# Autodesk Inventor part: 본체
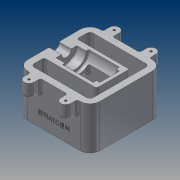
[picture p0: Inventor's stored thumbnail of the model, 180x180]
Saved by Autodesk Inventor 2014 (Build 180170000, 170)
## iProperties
Created: 2018-01
Part Number: 본체
Material: 알루미늄 6061
Document SubType Name: Modeling
Designer: user
Mass: 999.317 g
Surface Area: 835.945 cm^2
Volume: 368.752 cm^3
Density: 2.71 g/cm^3
Appearance: 알루미늄 - 평지
Author: user
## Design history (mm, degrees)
sketch "스케치2"
  geometry: L1 (-55, -55)-(55, -55); L2 (55, -55)-(55, 55); L3 (55, 55)-(-55, 55); L4 (-55, 55)-(-55, -55); L5 (-55, -55)-(55, 55); L6 (55, -55)-(-55, 55); L7 (-45, 45)-(45, 45); L8 (45, 45)-(45, -45); L9 (45, -45)-(-45, -45); L10 (-45, -45)-(-45, 45); L11 (-45, 45)-(45, -45); L12 (45, 45)-(-45, -45); 1 further point
  constraints: 24 end point, 4 midpoint, 4 parallel, 2 horizontal, 2 perpendicular
  dimensions: "d0" = 110 distance of L2.end L3.end; "d1" = 110 distance of L1.end L2.end; "d2" = 90 distance of L7.start L7.end; "d3" = 90 distance of L7.end L8.end
extrude "돌출1" new body sketch "스케치2" distance "d4" = 65; taper "d5" = 0 deg
fillet "모깎기1" dims "d6" = 15
fillet "모깎기2" dims "d7" = 5
sketch "스케치3"
  geometry: L1 (-55, 0)-(-55, 65) reference; L2 (-55, 65)-(35, 65); L3 (35, 65)-(35, 0); L4 (35, 0)-(-55, 0); L5 (-55, 0)-(-55, 65); L6 (40, 0)-(-40, 0) reference; L7 (55, 65)-(55, 0) reference; 2 further points
  constraints: 8 end point, 2 parallel, 1 horizontal, 1 horizontal alignment, 1 midpoint, 1 perpendicular
  dimensions: "d8" = 20 distance between parallel lines of L3 L7
extrude "돌출2" join sketch "스케치3" stored distance "d9" = 50; taper "d10" = 0 deg
sketch "스케치5"
  geometry: L1 (-55, 40)-(-55, -40) reference; L2 (-55, 0)-(35, 0); L3 (35, -25)-(35, 25) reference; L4 (-55, 0)-(-55, 7.5); L5 (-55, 7.5)-(-36, 7.5); L6 (-36, 7.5)-(-36, 16); L7 (-36, 16)-(-22, 16); L8 (-22, 16)-(-22, 20); L9 (-22, 20)-(25, 20); L10 (25, 20)-(25, 15); L11 (25, 15)-(30, 15); L12 (30, 15)-(30, 0); 1 further point
  constraints: 20 end point, 5 parallel, 4 perpendicular, 2 midpoint, 2 point on line
  dimensions: "d11" = 15 diameter of L5 L2; "d12" = 19 distance of L4.end L5.end; "d13" = 14 distance of L6.end L7.end; "d14" = 32 diameter of L7 L2; "d15" = 40 diameter of L9 L2; "d16" = 47 distance of L8.end L9.end; "d17" = 5 distance of L10.end L11.end; "d18" = 30 diameter of L11 L2
revolve "회전1" sketch "스케치5" stored, may be unused: angle "d19" = 90 deg
sketch "스케치6"
  geometry: L1 (25, 45)-(-22, 45) reference; L2 (35, 65)-(35, 0) reference; L3 (35, 0)-(-45, 0) reference; L4 (35, 30)-(-45, 8.564); L5 (-45, 8.564)-(-45, 0); L6 (-55, 0)-(-55, 65) reference; 1 further point
  constraints: 4 end point, 2 point on line, 1 perpendicular
  dimensions: "d20" = 30 distance of L2.end L4.start; "d21" = 105 deg angle of L4 L5; "d22" = 10 distance between parallel lines of L6 L5
extrude "돌출3" cut sketch "스케치6" stored distance "d23" = 50; taper "d24" = 0 deg
sketch "스케치7"
  geometry: L1 (35, 30)-(-45, 8.564) reference; L2 (20, 31.157)-(-55, 11.061); L3 (-55, 0)-(-55, 65) reference; L4 (-55, 29.061)-(-17, 39.243); L5 (-17, 39.243)-(-17, 51.224); L6 (-17, 51.224)-(20, 51.224); L7 (20, 51.224)-(20, 31.157); L8 (-22, 65)-(-22, 45) reference; 1 further point
  constraints: 10 end point, 4 parallel, 2 point on line, 1 perpendicular
  dimensions: "d25" = 5 distance between parallel lines of L2 L1; "d26" = 18 distance of L4.start L2.end; "d27" = 37 distance between parallel lines of L7 L5; "d28" = 5 distance between parallel lines of L8 L5
extrude "돌출4" cut sketch "스케치7" stored distance "d29" = 30; taper "d30" = 0 deg
fillet "모깎기3" dims "d31" = 1
chamfer "모따기1" distance "d32" = 1; stored, may be unused: second distance "d33" = 2, angle "d34" = 45 deg
fillet "모깎기4" dims "d35" = 3
sketch "스케치8"
  geometry: L1 (-55, 40)-(-55, 8.5) reference; L2 (40, 55)-(-40, 55) reference; L3 (-35.5, 65)-(-35.5, 55); L4 (-20.5, 65)-(-20.5, 55); L5 (20.5, 65)-(20.5, 55); L6 (35.5, 65)-(35.5, 55); A1 r 7.5 centre (-28, 65) between (-35.5, 65) and (-20.5, 65); A2 r 7.5 centre (28, 65) between (20.5, 65) and (35.5, 65); 1 further point
  constraints: 8 end point, 4 perpendicular, 4 point on circle, 4 point on line, 4 tangent, 2 centre point, 1 horizontal alignment
  dimensions: "d36" = 15 diameter of A1; "d38" = 10 distance from line of L2 A1.centre; "d39" = 15 diameter of A2; "d40" = 56 distance of A2.centre A1.centre; "d57" = 19.5 distance between parallel lines of L1 L3
extrude "돌출5" join sketch "스케치8" distance "d41" = 20; taper "d42" = 0 deg
sketch "스케치9"
  geometry: A1 r 7.5 centre (-28, 65) between (-20.5, 65) and (-35.5, 65) reference; A2 r 7.5 centre (28, 65) between (35.5, 65) and (20.5, 65) reference; 3 further points
  constraints: 2 coincident
hole "구멍1" sketch "스케치9" at (-28, 65), (28, 65) diameter "d43" = 3.242; stored, may be unused: countersink angle "d47" = 90 deg, drill point angle "d49" = 118 deg; dims "d44" = 9, "d45" = 4, "d46" = 2, "d48" = 11
fillet "모깎기5" dims "d50" = 3
fillet "모깎기6" dims "d51" = 3
sketch "스케치10"
  geometry: L1 (-15, 65)-(-15, 0) reference; 2 further points
  constraints: 1 other
  dimensions: "d52" = 55 distance from line of L1 point (40, 20); "d53" = 20 distance of point (40, 0) point (40, 20)
feature "엠보싱1" sketch "스케치10" dims "d0" = 110, "d1" = 110, "d54" = 0.5, "d55" = 0
fillet "모깎기7" dims "d56" = 3
node "솔리드1"
mirror "대칭1"
mirror "대칭2"
